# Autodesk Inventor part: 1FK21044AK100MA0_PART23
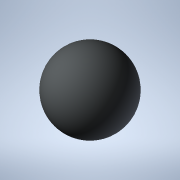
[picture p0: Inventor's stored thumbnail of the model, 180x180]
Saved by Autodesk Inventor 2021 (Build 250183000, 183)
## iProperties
Created: 2025-04
Part Number: 1FK21044AK100MA0_PART23
Material: Generic
Catalog Web Link: www.3dfindit.com
Description: -Servo synchronous motor
Document SubType Name: Modeling
Designer: psAdmin
Mass: 0.137258 g
Surface Area: 1.2868 cm^2
Volume: 0.137258 cm^3
Density: 1 g/cm^3
Appearance: PSOLRGB-212-217-219
Category: PARTsolutions
Title: 1FK21044AK100MA0_PART23
Author: Cadenas PARTsolutions
Comments: Servo synchronous motor
Sending System: PARTsolutions
Preprocessor: ST-DEVELOPER v19.3
PSOL_IDENT_0: {$CADENAS_DATA/23d-libs/siemens_ag/_cat_/5e/d8/1fk21044ak100ma0.prj},216 {VTYP=3D},{NB=1FK21044AK100
PSOL_IDENT_1: MA0_PART23},{LINA=1FK21044AK100MA0_PART23},{NN=1FK21044AK100MA0_PART23},{NOPRJ=TRUE},{DATE=19.08.202
PSOL_IDENT_2: 5 14:00:41},{GEOMDATE=30.07.2025 02:00:53},{VERSION=},{LINEID=10},{WBVAR=},{WBNUMERIC=}  {NB=1FK2104
PSOL_IDENT_3: 4AK100MA0_PART23},{LINA=1FK21044AK100MA0_PART23},{KT=DUMMY},{PREVIEW=../../../_pool_/cb/72/p_d211_xx
PSOL_IDENT_4: _00434j.png},{DESCSHORT=SIMOTICS S-1FK2 HD, SINAMICS S210 3AC 400V-480V, 0.95 Nm, 6000 rpm},{DESCLON
PSOL_IDENT_5: G=SIMOTICS S-1FK2 HD servo motor M0=1.27 Nm; PN = 0.6 kW at nN=6000 rpm (380-480 V); PN = 0.4 kW at
PSOL_IDENT_6: nN=3000 rpm (200-240 V); with holding brake; degree of protection IP64; cylindrical shaft D19x40mm;
PSOL_IDENT_7: absolute encoder 22-bit + 12-bit multiturn (encoder AM22DQC); with OCC interface; plug size M17, rot
PSOL_IDENT_8: atable; SIMOTICS S-1FK2 servomotorfor a wide range of uses in industrial environments. SIMOTICS S‑1F
PSOL_IDENT_9: K2 servomotors are compact synchronous motors with a high dynamic performance that set themselves ap
PSOL_IDENT_10: art as a result of their high power density, degree of protection and overload capability. The motor
PSOL_IDENT_11: s are available in two variants: as High Dynamic variant (highest dynamic performance as a result of
PSOL_IDENT_12: the low intrinsic moment of inertia for applications demanding a high dynamic performance with low
PSOL_IDENT_13: moved masses) - and as Compact variant (precise and stable closed-loop control for medium up to larg
PSOL_IDENT_14: e moved masses as a result of a medium intrinsic moment of inertia). SIMOTICSS‑1FK2 servomotors full
PSOL_IDENT_15: y exploit their strengths in a system with the SINAMICSS210 frequency converter and simple connectio
PSOL_IDENT_16: n using the one cable connection (OCC). Advantages include the short control and positioning times,
PSOL_IDENT_17: fast and precise correction of disturbing quantities as well as stable control with a high dynamic p
PSOL_IDENT_18: erformance. The servo motors can be configured to address a wide range of requirements. For example
PSOL_IDENT_19: with and without holding brake, IP64 or IP65 degree of protection, singleturn or multiturn absolute
PSOL_IDENT_20: encoders - to name just a few. Further, the servomotors are available in different shaft heights ext
PSOL_IDENT_21: ending from 20 to 100. A shaft sealing ring is available to achieve an IP65 degree of protection and
PSOL_IDENT_22: for subsequent mounting at the motor or as spare part. SIMOTICS - the optimum motor for each and ev
PSOL_IDENT_23: ery motion control application.},{INTNO=804766910005},{SUPPLIERALTNO=1FK2104-4AK10-0MA0},{MANUID=1FK
PSOL_IDENT_24: 21044AK100MA0},{MANUNAME=Siemens},{MANUTYPEDESC=Synchronous motor 1FK2-HD 1,27 Nm},{AAU732=SIMOTICS}
PSOL_IDENT_25: ,{AAO057=S-1FK2},{AAU734=SIMOTICS S-1FK2 HD servo motor M0=1.27 Nm; PN = 0.6 kW at nN=6000 rpm (380-
PSOL_IDENT_26: 480 V); PN = 0.4 kW at nN=3000 rpm (200-240 V); with holding brake; degree of protection IP64; cylin
PSOL_IDENT_27: drical shaft D19x40mm; absolute encoder 22-bit + 12-bit multiturn (encoder AM22DQC); with OCC interf
PSOL_IDENT_28: ace; plug size M17, rotatable;},{AAW338=Synchronous motor 1FK2-HD 1,27 Nm},{AAO742=SIMOTICS},{AAO663=
PSOL_IDENT_29: 4042948691076},{NOCUPEROU=1},{PRICEQUANTITY=1},{QUANTITYMIN=1},{QUANTITYINT=1},{CTN=85015100},{COO=D
PSOL_IDENT_30: E},{AAO676=1FK2104-4AK10-0MA0},{AAO677=Siemens AG},{ORDERUNIT=C62},{CONTENTUNIT=C62}
NB: 1FK21044AK100MA0_PART23
NT: Servo synchronous motor
NBSYN: $MANUID._PART23
LINA: 1FK21044AK100MA0_PART23
CATALOG: SIEMENS
PREVIEW: ../../../_pool_/cb/72/p_d211_xx_00434j.png
DESCSHORT: SIMOTICS S-1FK2 HD, SINAMICS S210 3AC 400V-480V, 0.95 Nm, 6000 rpm
DESCLONG: SIMOTICS S-1FK2 HD servo motor M0=1.27 Nm; PN = 0.6 kW at nN=6000 rpm (380-480 V); PN = 0.4 kW at nN=3000 rpm (200-240 V); with holding brake; degree of protect
INTNO: 804766910005
SUPPLIERALTNO: 1FK2104-4AK10-0MA0
MANUID: 1FK21044AK100MA0
MANUNAME: Siemens
MANUTYPEDESC: Synchronous motor 1FK2-HD 1,27 Nm
AAU732: SIMOTICS
AAO057: S-1FK2
AAU734: SIMOTICS S-1FK2 HD servo motor M0=1.27 Nm; PN = 0.6 kW at nN=6000 rpm (380-480 V); PN = 0.4 kW at nN=3000 rpm (200-240 V); with holding brake; degree of protect
AAW338: Synchronous motor 1FK2-HD 1,27 Nm
AAO742: SIMOTICS
AAO663: 4042948691076.0
NOCUPEROU: 1
PRICEQUANTITY: 1
QUANTITYMIN: 1
QUANTITYINT: 1
CTN: 85015100
COO: DE
ARTICLENO: 1FK21044AK100MA0_PART23
BOMINFO: 1FK21044AK100MA0_PART23
CREATOR: CADENAS GmbH
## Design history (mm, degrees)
feature "2025_04_17_15_35_41_0968"
body "Solid1"
